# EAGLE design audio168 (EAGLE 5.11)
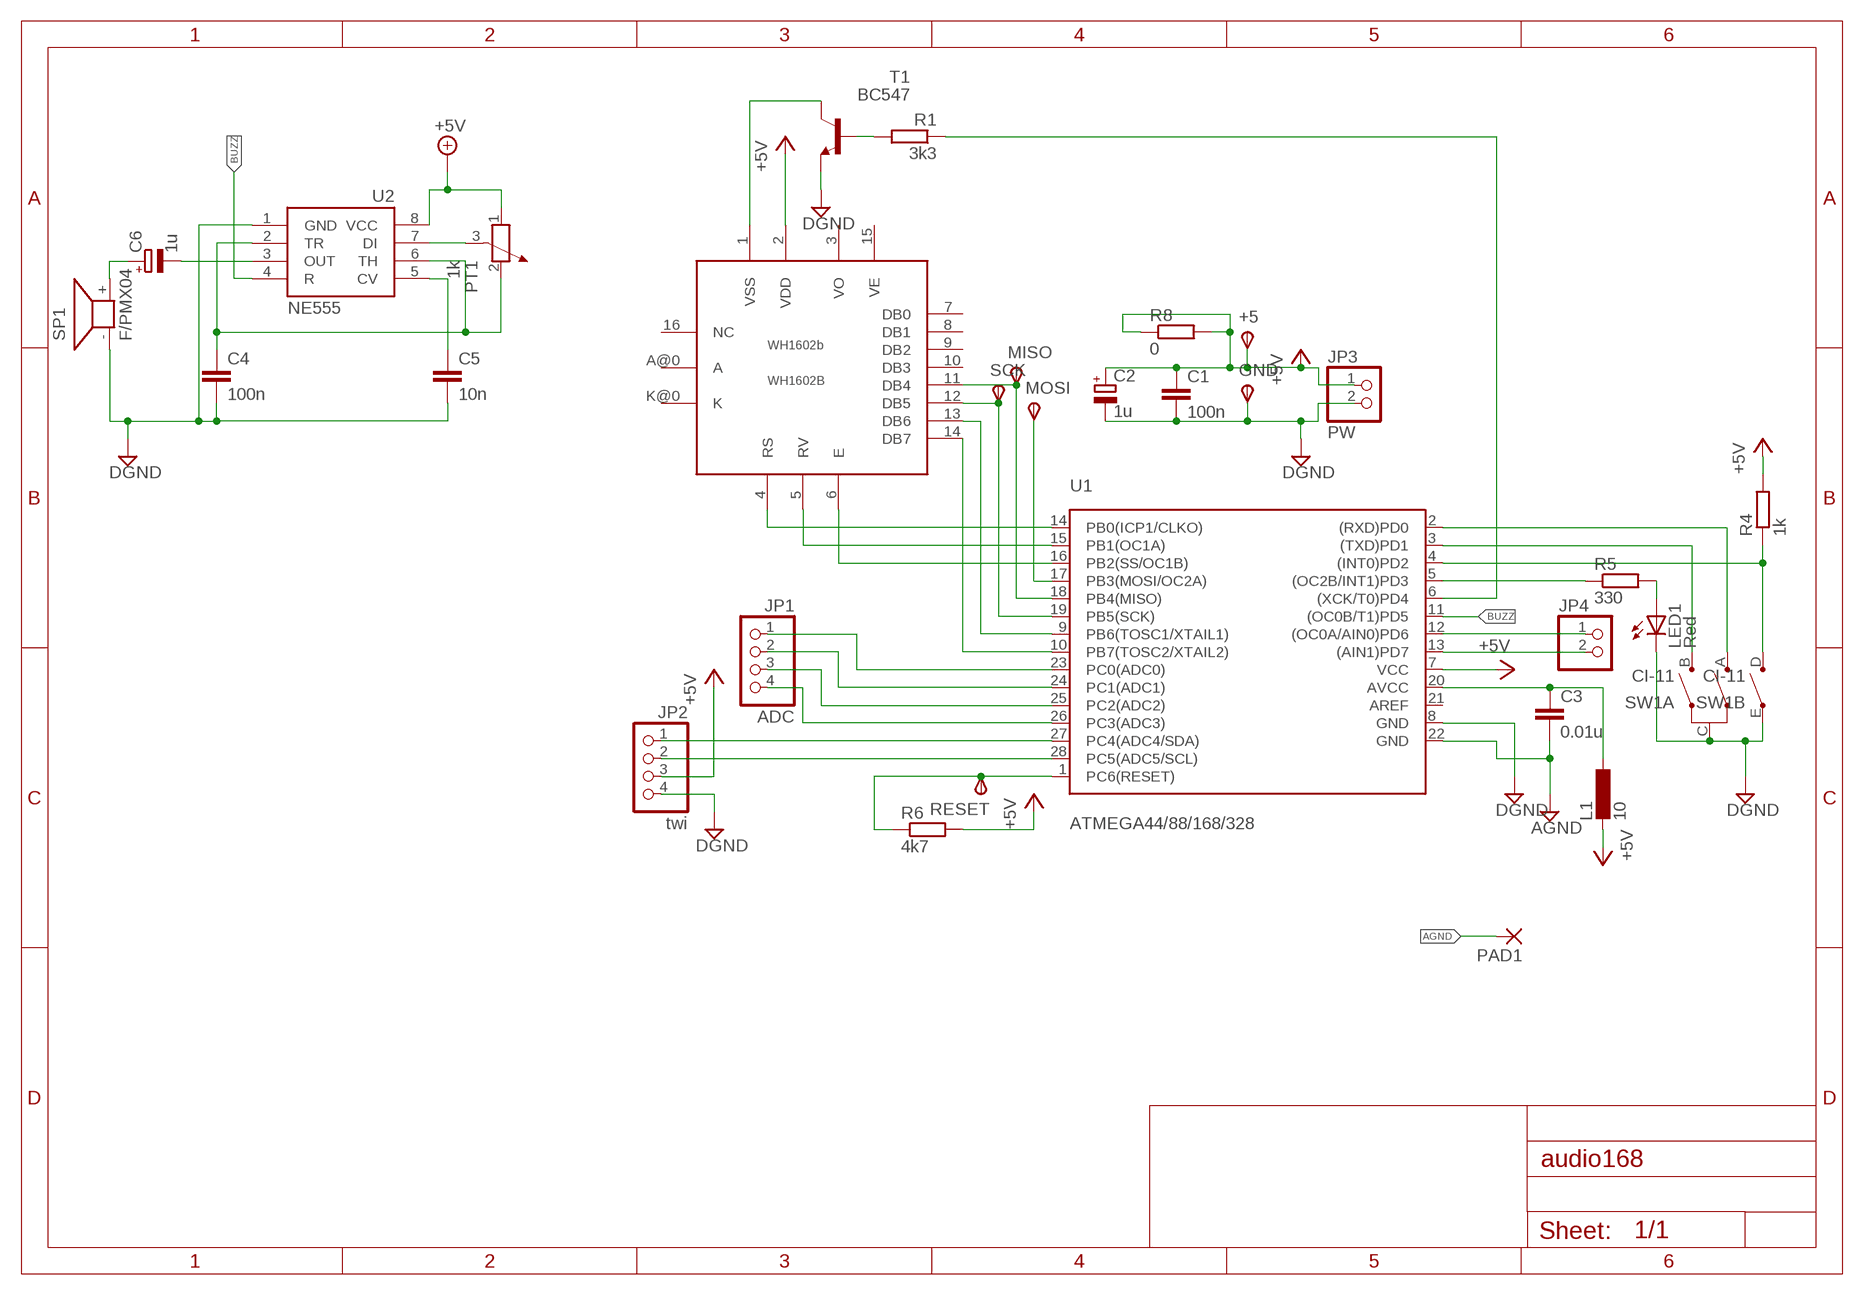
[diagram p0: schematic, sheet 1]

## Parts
+5  TPSTP20SQ  [TP20SQ]
C1  100n  C-EUC1206  [C1206]
C2  1u  CPOL-EUSMCC  [SMC_C]
C3  0.01u  C-EUC1206  [C1206]
C4  100n  C-EU050-035X075  [C050-035X075]
C5  10n  C-EU050-030X075  [C050-030X075]
C6  1u  CPOL-EUE2.5-7  [E2,5-7]
GND  TPSTP20SQ  [TP20SQ]
JP1  ADC  PINHD-1X4  [1X04]
JP2  twi  PINHD-1X4  [1X04]
JP3  PW  PINHD-1X2  [1X02]
JP4  PINHD-1X2  [1X02]
L1  10  L-EU0204/7  [0204/7]
LED1  Red  LED3MM  [LED3MM]
MISO  TPSTP20SQ  [TP20SQ]
MOSI  TPSTP20SQ  [TP20SQ]
PAD1  2,54/1,1  [2,54/1,1]
PT1  1k  POTE  [PT-20]
R1  3k3  R-EU_M1206  [M1206]
R4  1k  R-EU_M1206  [M1206]
R5  330  R-EU_M1206  [M1206]
R6  4k7  R-EU_M1206  [M1206]
R8  0  R-EU_M1206  [M1206]
RESET  TPSTP20SQ  [TP20SQ]
SCK  TPSTP20SQ  [TP20SQ]
SP1  F/PMX04  [F/PMX04A]
SW1  CI-11  [CI-11]
T1  BC547  [TO92]
U1  ATMEGA44/88/168/328  [DIL28-3]
U2  NE555  [DIL08]
U$1  WH1602B  [WH1602B]

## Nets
+5V: +5.TP(PP) C1.1 C2.+ JP2.3 JP3.1 L1.2 PT1.1 R4.2 R6.2 R8.1 R8.2 U1.7(VCC) U2.8(VCC) U$1.2(VDD)
ADC0: JP1.1 U1.23(PC0(ADC0))
ADC1: JP1.2 U1.24(PC1(ADC1))
ADC2: JP1.3 U1.25(PC2(ADC2))
ADC3: JP1.4 U1.26(PC3(ADC3))
AGND: C3.2 PAD1.1(P) U1.22(GND)
BUZZ: U1.11((OC0B/T1)PD5) U2.4(R)
DGND: C1.2 C2.- C4.2 C5.2 GND.TP(PP) JP2.4 JP3.2 LED1.K(C) SP1.- SW1.C(A:C) SW1.E(B:E) T1.1(E) U1.8(GND) U2.1(GND)
LCDON: R1.1 U1.6((XCK/T0)PD4)
N$1: MOSI.TP(PP) U1.17(PB3(MOSI/OC2A))
N$2: U1.14(PB0(ICP1/CLKO)) U$1.4(RS)
N$3: C3.1 L1.1 U1.20(AVCC)
N$7: U1.10(PB7(TOSC2/XTAIL2)) U$1.14(DB7)
N$9: U1.9(PB6(TOSC1/XTAIL1)) U$1.13(DB6)
N$10: SCK.TP(PP) U1.19(PB5(SCK)) U$1.12(DB5)
N$12: MISO.TP(PP) U1.18(PB4(MISO)) U$1.11(DB4)
N$13: R6.1 RESET.TP(PP) U1.1(PC6(RESET))
N$14: T1.3(C) U$1.1(VSS)
N$15: R1.2 T1.2(B)
N$16: SW1.A(A:A) U1.2((RXD)PD0)
N$17: SW1.B(A:B) U1.3((TXD)PD1)
N$18: R4.1 SW1.D(B:D) U1.4((INT0)PD2)
N$19: C4.1 PT1.2 U2.2(TR) U2.6(TH)
N$20: LED1.A R5.2
N$21: R5.1 U1.5((OC2B/INT1)PD3)
N$22: U1.15(PB1(OC1A)) U$1.5(RV)
N$23: U1.16(PB2(SS/OC1B)) U$1.6(E)
N$24: C5.1 U2.5(CV)
N$28: C6.+ SP1.+
N$29: C6.- U2.3(OUT)
N$31: PT1.3 U2.7(DI)
SCL: JP2.2 U1.28(PC5(ADC5/SCL))
SDA: JP2.1 U1.27(PC4(ADC4/SDA))
SV2: JP4.1 U1.12((OC0A/AIN0)PD6)
SV3: JP4.2 U1.13((AIN1)PD7)
Unconnected: U1.21(AREF) U$1.3(VO) U$1.7(DB0) U$1.8(DB1) U$1.9(DB2) U$1.10(DB3) U$1.15(VE) U$1.16(NC) U$1.A@0(A) U$1.K@0(K)

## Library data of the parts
+5 GND MISO MOSI RESET SCK = testpad:TPS: TEST PIN
C1 C3-C5 = rcl:C-EU: CAPACITOR, European symbol
C2 C6 = rcl:CPOL-EU: POLARIZED CAPACITOR, European symbol
JP1 JP2 = pinhead:PINHD-1X4: PIN HEADER
JP3 JP4 = pinhead:PINHD-1X2: PIN HEADER
L1 = rcl:L-EU: INDUCTOR, European symbol
LED1 = led:LED: LED
PAD1 = wirepad:2,54/1,1: THROUGH-HOLE PAD
PT1 = ds:POTE
R1 R4-R6 R8 = resistor:R-EU_: RESISTOR, European symbol
SP1 = ds:F/PMX04: SPEAKER
SW1 = piher:CI-11: 11mm Incemental Encoder Source: www.piher.net .. 04-CI-11v04.pdf
T1 = transistor:BC547: NPN TRANSISTOR
U1 = ds:ATMEGA44/88/168/328: ATMEGA 44/88/168/328 High Performance, Low Power Atmel® AVR® 8-Bit Microcontroller Advanced RISC Architecture ? 131 Powerful Instructions ? Most Single Clock Cycle Execution ? 32 × 8 General Purpose Working Registers ? Fully Static Operation ? Up to 20 MIPS Throughput at 20 MHz ? On-chip 2-cycle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
U2 = ds:NE555: Features High Current Drive Capability (200mA) Adjustable Duty Cycle Temperature Stability of 0.005%/°C Timing From Sec To Hours Turn Off Time Less Than 2uSec
U$1 = ds:WH1602B; WH1602B: U

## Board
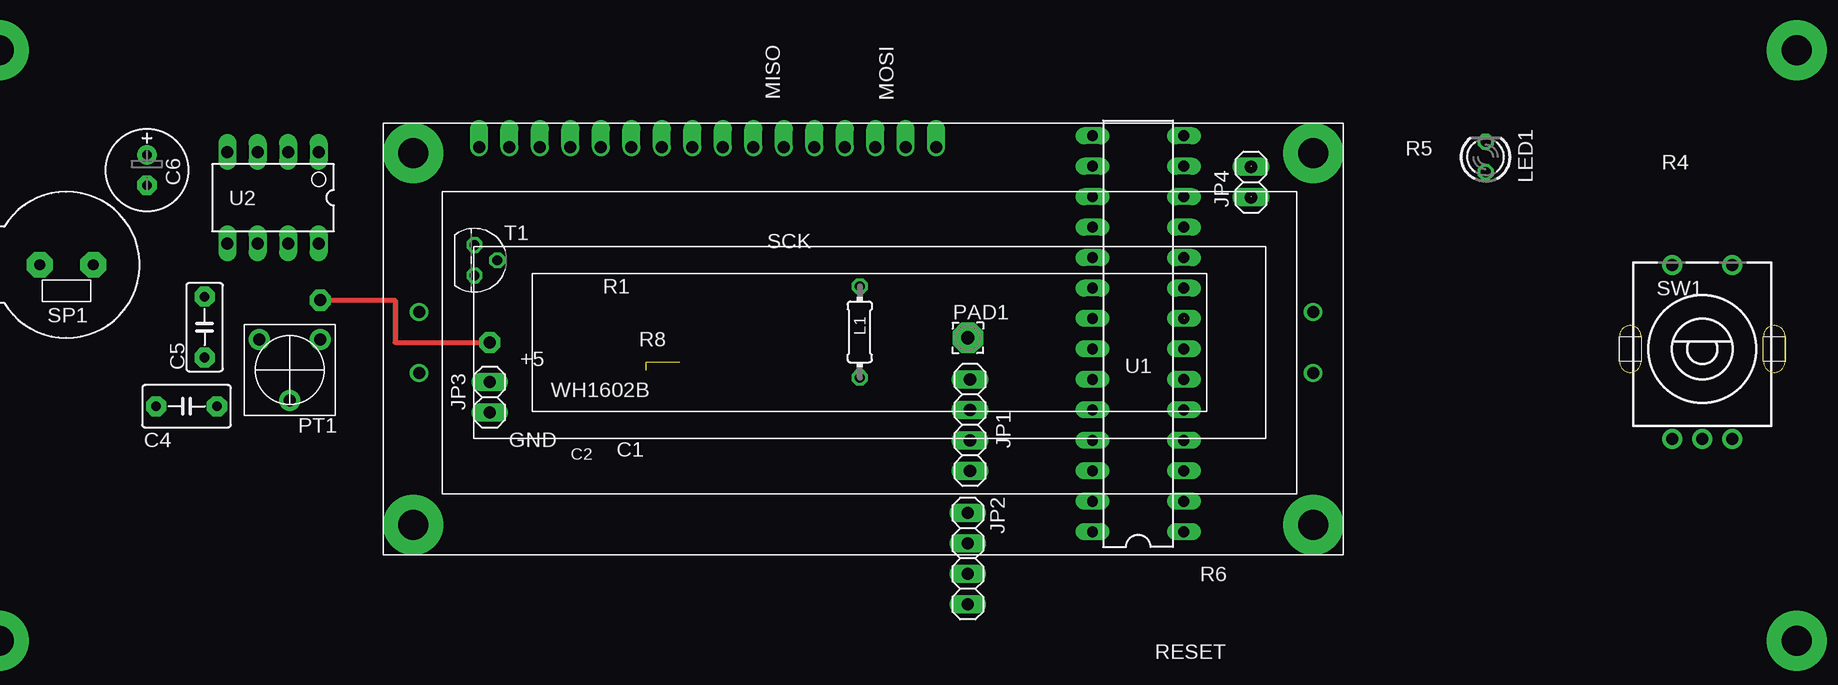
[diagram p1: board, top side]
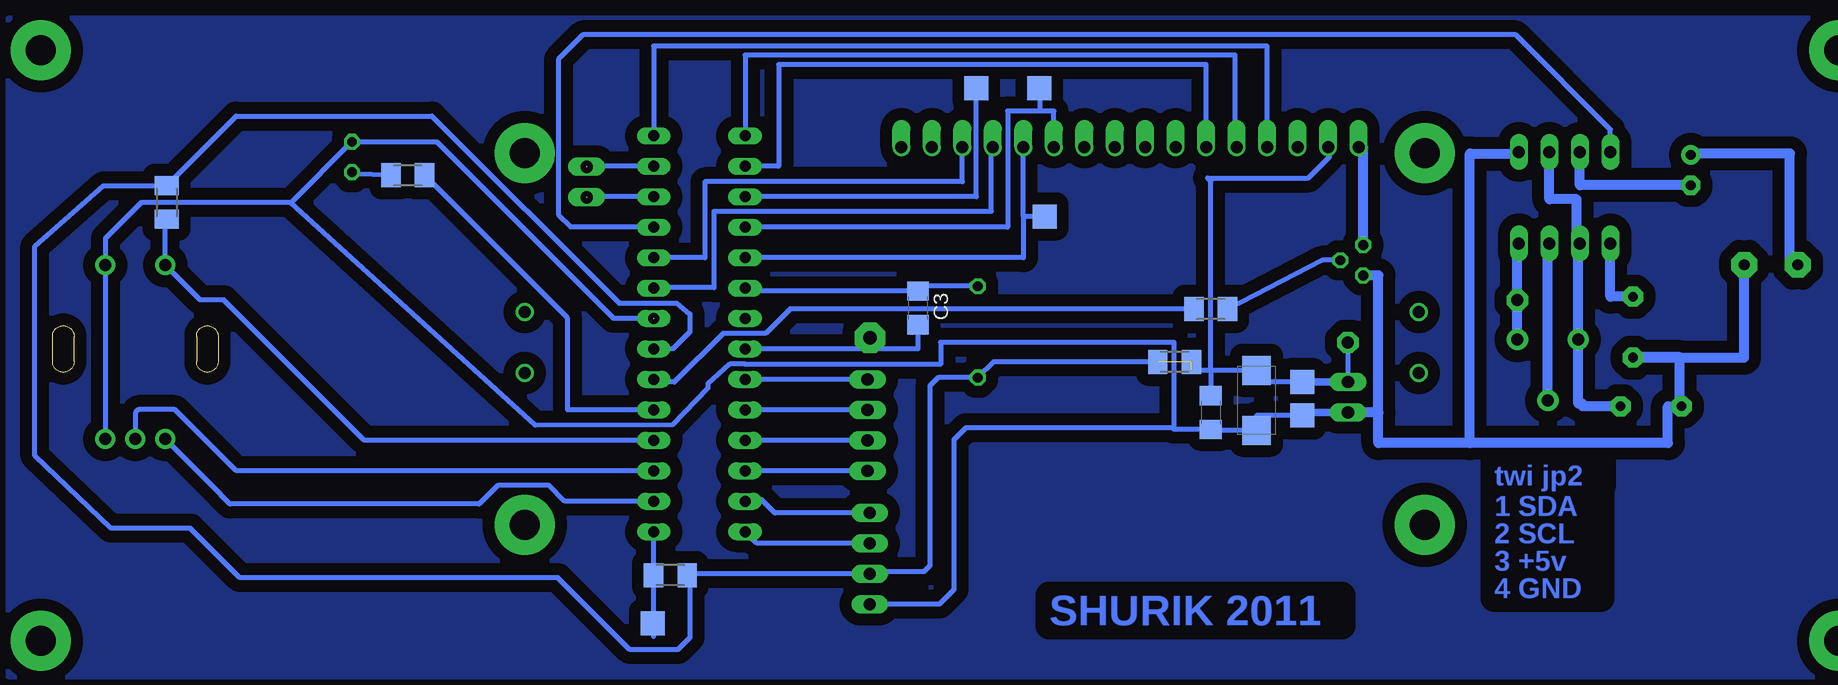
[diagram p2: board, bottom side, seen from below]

Size 13.8 x 3.9 mm. Coordinates in mm from the lower left corner, seen from the top.
Copper layers (1*16): Top 0.035mm / dielectric 1.5mm / Bottom 0.035mm
Design rules "default": minimum track width 10mil, minimum drill 24mil, track to track 8mil, track to pad 8mil, pad to pad 8mil, via to via 8mil, smd to smd 8mil, copper to edge 40mil, drill to drill 8mil, minimum pad ring 10mil, minimum via ring 8mil, stop-mask expansion 4mil, vias tented up to drill 0mil, thermal gap 10mil
bRestrict: area -115.2,-18.8 to -106.3,-7.7; area -93.6,-21.1 to -69.3,-18.6

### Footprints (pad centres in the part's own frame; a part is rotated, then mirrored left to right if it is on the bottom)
TP20SQ = smd 2 x 2: TP 0,0
C1206 = smd 1.6 x 1.8: 1 -1.4,0; 2 1.4,0
SMC_C = smd 2.4 x 2.4: + -2.5,0; - 2.5,0
C050-035X075 = drill 0.813 pad 1.676 octagon: 1 -2.54,0; 2 2.54,0
C050-030X075 = drill 0.813 pad 1.676 octagon: 1 -2.54,0; 2 2.54,0
E2,5-7 = drill 0.813 pad 1.6 round: + -1.27,0 | drill 0.813 pad 1.6 octagon: - 1.27,0
1X04 = drill 1.016 long: 1 -3.81,0; 2 -1.27,0; 3 1.27,0; 4 3.81,0
1X02 = drill 1.016 long: 1 -1.27,0; 2 1.27,0
0204/7 = drill 0.813 octagon: 1 -3.81,0; 2 3.81,0
LED3MM = drill 0.813 octagon: A -1.27,0; K 1.27,0
2,54/1,1 = drill 1.118 pad 2.54 octagon: 1 0,0
PT-20 = drill 1 pad 1.778 round: 1 -2.54,-1.27; 2 2.54,-1.27; 3 0,3.81
M1206 = smd 1.6 x 2: 1 -1.4,0; 2 1.4,0
F/PMX04A = drill 0.914 pad 2.159 octagon: + 2.235,0; - -2.235,0
CI-11 = drill 1 pad 1.676 round: A -2.5,-7.5; B 0,-7.5; C 2.5,-7.5; D -2.5,7; E 2.5,7
TO92 = drill 0.813 octagon: 1 1.27,0; 2 0,1.905; 3 -1.27,0
DIL28-3 = drill 0.9 long: 1 -16.51,-3.81; 2 -13.97,-3.81; 3 -11.43,-3.81; 4 -8.89,-3.81; 5 -6.35,-3.81; 6 -3.81,-3.81; 7 -1.27,-3.81; 8 1.27,-3.81; 9 3.81,-3.81; 10 6.35,-3.81; 11 8.89,-3.81; 12 11.43,-3.81; 13 13.97,-3.81; 14 16.51,-3.81; 15 16.51,3.81; 16 13.97,3.81; 17 11.43,3.81; 18 8.89,3.81; 19 6.35,3.81; 20 3.81,3.81; 21 1.27,3.81; 22 -1.27,3.81; 23 -3.81,3.81; 24 -6.35,3.81; 25 -8.89,3.81; 26 -11.43,3.81; 27 -13.97,3.81; 28 -16.51,3.81
DIL08 = drill 1 long: 1 -3.81,-3.81; 2 -1.27,-3.81; 3 1.27,-3.81; 4 3.81,-3.81; 5 3.81,3.81; 6 1.27,3.81; 7 -1.27,3.81; 8 -3.81,3.81
WH1602B = drill 1 offset: 1 8,-2; 2 10.54,-2; 3 13.08,-2; 4 15.62,-2; 5 18.16,-2; 6 20.7,-2; 7 23.24,-2; 8 25.78,-2; 9 28.32,-2; 10 30.86,-2; 11 33.4,-2; 12 35.94,-2; 13 38.48,-2; 14 41.02,-2; 15 43.56,-2; 16 46.1,-2 | drill 1 pad 1.5 round: A@0 3,-20.84; A@1 77.5,-15.76; K@0 3,-15.76; K@1 77.5,-20.84 | drill 2.5 pad 5 round: F@0 2.5,-2.5; F@1 77.5,-2.5; F@2 2.5,-33.5; F@3 77.5,-33.5

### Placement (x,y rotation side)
+5  -90.34,-0.81 0 bottom  (outside the outline)
C1  -82.72,-3.35 270 bottom  (outside the outline)
C2  -86.53,-2.34 270 bottom  (outside the outline)
C3  -58.31,5.37 270 bottom  (outside the outline)
C4  -119.41,-2.83 180 top  (outside the outline)
C5  -117.91,3.77 270 top  (outside the outline)
C6  -122.71,16.87 270 top  (outside the outline)
GND  -90.34,-3.61 0 bottom  (outside the outline)
JP1  -54.12,-4.4 270 top  (outside the outline)
JP2  -54.31,-15.53 270 top  (outside the outline)
JP3  -94.15,-2.08 270 top  (outside the outline)
JP4  not placed on the board
L1  -63.31,3.37 270 top  (outside the outline)
LED1  -11.15,17.96 90 top  (outside the outline)
MISO  -68.42,23.68 0 bottom  (outside the outline)
MOSI  -63.19,23.68 0 bottom  (outside the outline)
PAD1  -54.31,2.87 0 top  (outside the outline)
PT1  -110.81,1.47 180 top  (outside the outline)
R1  -82.72,5.28 0 bottom  (outside the outline)
R4  4.3,14.17 90 bottom  (outside the outline)
R5  -15.81,16.43 180 bottom  (outside the outline)
R6  -37.69,-16.91 0 bottom  (outside the outline)
R8  -79.71,0.87 0 bottom  (outside the outline)
RESET  -36.23,-20.91 0 bottom  (outside the outline)
SCK  -68.87,13 0 bottom  (outside the outline)
SP1  -129.41,8.97 180 top  (outside the outline)
SW1  6.9,1.95 0 top
T1  -95.42,9.35 270 top  (outside the outline)
U1  -40.11,3.22 90 top  (outside the outline)
U2  -112.21,14.57 180 top  (outside the outline)
U$1  -103.04,20.78 0 top  (outside the outline)

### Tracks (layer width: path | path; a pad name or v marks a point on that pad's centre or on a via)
+5V  (via drill 1 pad 1.78)  (2 unrouted)
  Top 0.406: v-108.27,6.01 -102.02,6.01 -102.02,2.49 v-94.15,2.49
  Bottom 0.406: -82.72,0.16 C2.+ -86.53,-0.81 +5.TP | -82.72,0.16 C1.1 | -82.72,0.16 -82.72,15.95 -82.47,16.21 -90.85,16.21 -92.63,17.98 -92.63,18.65 U$1.2 | -82.72,0.16 -81.11,0.16 | U1.7 -37.89,1.95 -39.31,3.37 -39.31,4.87 -38.21,5.77 -33.41,5.77 -17.81,21.37 -1.5,21.37 R4.2 9.56,15.57 15.27,10.52 15.27,-6.96 8.93,-13 2.32,-13 -1.81,-17.13 -28.31,-17.13 -34.31,-23.13 -38.31,-23.13 -39.31,-22.13 -39.31,-17.14 R6.2 -39.2,-16.8 JP2.3 -54.48,-16.63 -58.81,-16.63 -59.31,-16.13 -59.31,-1.13 -60,-0.44 L1.2 -64.62,0.87 R8.1 | v-94.15,2.49 JP3.1
  Bottom 0.61: JP3.1 +5.TP
  Bottom 0.813: U2.8 -108.27,10.76 v-108.27,6.01 PT1.1
ADC0
  Bottom 0.406: JP1.1 U1.23
ADC1
  Bottom 0.406: JP1.2 U1.24
ADC2
  Bottom 0.406: JP1.3 U1.25
ADC3
  Bottom 0.406: JP1.4 U1.26
AGND
  Bottom 0.406: -54.41,1.95 -58.31,1.95 C3.2 | -54.41,1.95 U1.22 | PAD1.1 -54.41,2.87 -54.41,1.95
BUZZ
  Bottom 0.406: U2.4 -116.02,20.24 -108.12,28.14 -30.4,28.14 -28.36,26.11 -28.36,13.16 -29.38,12.14 -36.27,12.14 U1.11
DGND  (1 unrouted)
  Bottom 0.406: SW1.C SW1.E 9.4,11.16 6.39,14.17 -6.01,14.17 | -6.01,14.17 -6.1,14.17 LED1.K -18.23,19.23 -32.94,4.52 -36.27,4.52 | -6.01,14.17 -26.43,-4.41 -37.86,-4.37 -40.81,-1.32 -40.81,-0.95 -42.64,0.68 -43.91,0.68 | -43.91,0.68 -43.99,0.68 | GND.TP -86.53,-3.61 C2.- -82.72,-4.84 C1.2 -79.67,-4.75 | -79.67,-4.75 -79.67,2.49 -60.21,2.49 -60.21,0.67 -43.91,0.67 -43.91,0.68 | JP2.4 -60.1,-19.34 -61.31,-18.13 -61.31,-5.63 -62.31,-4.63 -79.55,-4.63 -79.67,-4.75
  Bottom 0.61: JP3.2 -90.34,-3.35 GND.TP
  Bottom 0.813: T1.1 -96.69,8.08 -96.69,-3.35 | -96.69,-3.35 JP3.2 | SP1.- -127.17,1.23 C5.2 -117.91,1.27 -121.81,1.27 -121.81,-2.83 C4.2 -120.82,-2.83 -120.82,-5.89 -104.31,-5.89 | -104.31,-5.89 -104.31,18.24 -108.4,18.24 U2.1 | -96.69,-3.35 -96.69,-5.89 -104.31,-5.89
LCDON
  Bottom 0.406: R1.1 -47.67,5.28 -45.64,3.25 -42.08,3.25 -38.02,-0.81 -36.52,-0.81 U1.6
N$1
  Bottom 0.406: U1.17 -63.19,14.65 MOSI.TP
N$2
  Bottom 0.406: U$1.4 -87.41,27.21 -36.3,27.21 U1.14
N$3
  Bottom 0.406: L1.1 -58.72,7.18 C3.1 -44.18,6.77 U1.20
N$4  (via drill 2.5 pad 5)
  other vias: -135.08,26.86
N$5  (via drill 2.5 pad 5)
  other vias: -135.08,-22.4
N$6
  pour Bottom (isolate 1): 17.49,-25.33 -137.91,-25.33 -137.91,29.47 17.49,29.47
N$7
  Bottom 0.406: U1.10 -40.56,9.57 -40.56,15.9 -62.02,15.9 U$1.14
N$8  (via drill 2.5 pad 5)
  other vias: 14.78,-22.4
N$9
  Bottom 0.406: U$1.13 -64.43,18.78 -64.43,13.41 -41.32,13.41 -41.32,7.06 -36.3,7.06 U1.9
N$10
  Bottom 0.406: U1.19 -67.1,9.57 -67.1,13 | -67.1,13 U$1.12 | SCK.TP -67.1,13
N$11  (via drill 2.5 pad 5)
  other vias: 14.78,26.86
N$12
  Bottom 0.406: U1.18 -65.8,12.11 -65.8,21.79 -68.5,21.79 | -68.5,21.79 -69.64,21.79 U$1.11 | MISO.TP -68.5,22.92 -68.5,21.79
N$13
  Bottom 0.406: RESET.TP -36.29,-22.01 R6.1 U1.1
N$14
  Bottom 0.813: U$1.1 -95.42,18.78 T1.3
N$15
  Bottom 0.406: T1.2 -91.99,9.35 R1.2
N$16
  Bottom 0.406: U1.2 -28.91,-10.75 -27.6,-9.45 -23.28,-9.45 -21.76,-10.97 -0.98,-10.97 -0.22,-10.21 -0.22,-10.17 SW1.A
N$17
  Bottom 0.406: U1.3 -1.52,-8.21 3.59,-3.1 6.64,-3.1 6.9,-3.35 SW1.B
N$18
  Bottom 0.406: U1.4 -12.19,-5.67 -0.47,6.05 1.5,6.05 SW1.D 4.4,12.41 R4.1
N$19
  Bottom 0.813: -113.35,10.76 U2.6 | -113.35,10.76 PT1.2 -113.35,-2.63 -113.71,-2.63 -113.71,-2.83 C4.1 | -113.35,10.76 -113.2,10.76 -113.2,14.43 -110.94,14.43 U2.2
N$20
  Bottom 0.406: R5.2 -11.32,16.52 LED1.A
N$21
  Bottom 0.406: U1.5 -29.12,-3.13 -29.13,-2.62 -29.13,4.52 R5.1
N$22
  Bottom 0.406: U$1.5 -84.76,18.78 -84.76,26.46 -43.92,26.46 U1.15
N$23
  Bottom 0.406: U1.16 -46.71,17.19 -46.71,25.66 -82.34,25.66 U$1.6
N$24
  Bottom 0.813: C5.1 -116.02,6.31 U2.5
N$28
  Bottom 0.813: SP1.+ -130.98,8.97 -130.98,18.24 -122.71,18.24 C6.+
N$29
  Bottom 0.813: C6.- -113.48,15.6 U2.3
N$31
  Bottom 0.813: U2.7 -110.81,10.76 PT1.3
SCL
  Bottom 0.406: JP2.2 -44.89,-14.26 U1.28
SDA
  Bottom 0.406: JP2.1 -46.4,-11.72 -45.31,-10.63 -44.04,-10.63 U1.27
SV2  (1 unrouted)
  Bottom 0.406: U1.12 -30.68,14.65
SV3  (1 unrouted)
  Bottom 0.406: U1.13 -30.68,17.19

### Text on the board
Bottom: twi jp2 | 1 SDA | 2 SCL | 3 +5v | 4 GND | SHURIK 2011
